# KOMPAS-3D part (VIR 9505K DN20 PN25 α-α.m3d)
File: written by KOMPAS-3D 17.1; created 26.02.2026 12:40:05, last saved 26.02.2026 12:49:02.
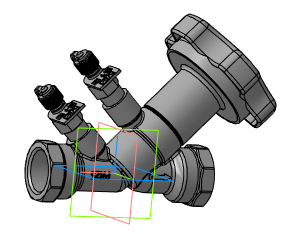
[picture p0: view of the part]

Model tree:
1. Операция без истории:4  (labels: VIR 9505K DN20 PN25 р-р)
